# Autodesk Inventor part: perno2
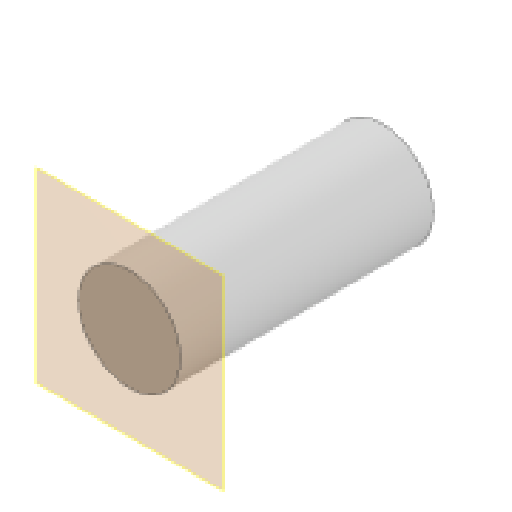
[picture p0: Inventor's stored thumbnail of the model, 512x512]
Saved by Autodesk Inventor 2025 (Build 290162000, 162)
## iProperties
Created: 2025-10
Part Number: perno2
Material: Generico
Document SubType Name: Modeling
Designer: Ryzen5700u
Density: 1 g/cm^3
Appearance: Default
Author: Ryzen5700u
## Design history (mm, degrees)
node "Piano di lavoro1"
sketch "Schizzo1"
  geometry: C1 r 13.5 at (0, 0); 1 further point
  constraints: 1 centre point, 1 coincident
  dimensions: "d0" = 27 diameter of C1
extrude "Estrusione1" new body sketch "Schizzo1" distance "d1" = 67; taper "d2" = 0 deg
node "Solido1"
